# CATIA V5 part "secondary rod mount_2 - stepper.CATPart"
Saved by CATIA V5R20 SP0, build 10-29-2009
Part number: secondary rod mount_2 - stepper
Source: Unknown
Bounding box of the stored display mesh (mm): x 0 to 57.3, y -10 to 78.3, z -46 to 0
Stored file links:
  C:\Users\Ikarus\OneDrive - FH JOANNEUM\BAC - Arbeit 1\CAD Modell\CAD-Modell-Step files\rod mount\secondary\secondary rod mount_2 - stepper.CATPart
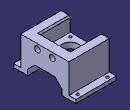
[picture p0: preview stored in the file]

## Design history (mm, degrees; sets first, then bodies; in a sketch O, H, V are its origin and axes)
Body1 (main body)
  Solid1 "Hauptkörper": solid without history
